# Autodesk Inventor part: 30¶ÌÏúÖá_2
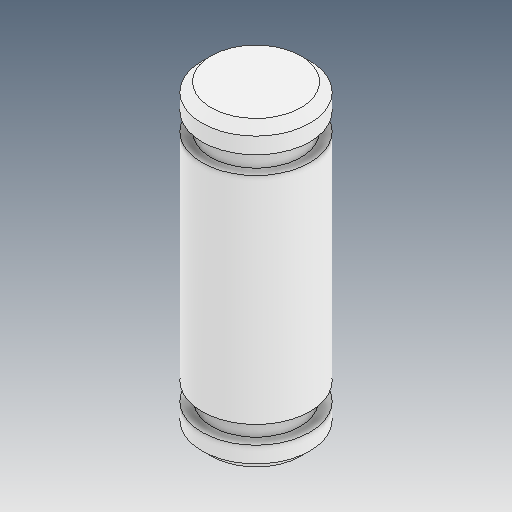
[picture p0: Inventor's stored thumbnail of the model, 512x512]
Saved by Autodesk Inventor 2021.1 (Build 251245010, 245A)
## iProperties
Created: 2021-05
Part Number: 30¶ÌÏúÖá_2
Material: Ogólny
Document SubType Name: Modeling
Designer: user
Density: 1 g/cm^3
Appearance: Domyślna
Author: user
Revision Number: ÈÎºÎ
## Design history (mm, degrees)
feature "ÊäÈë1"
node "Bryła1"
